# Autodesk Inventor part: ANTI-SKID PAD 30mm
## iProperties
Created: 2007-03
Part Number: ANTI-SKID PAD 30mm
Material: Rubber
Document SubType Name: Modeling
Designer: Andy Moles
Density: 0.93 g/cm^3
Mass: 1.73545 g
Surface Area: 13.5563 cm^2
Volume: 1.86608 cm^3
Author: Andy Moles
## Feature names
1. Extrusion1
2. Extrusion2
3. Fillet1
